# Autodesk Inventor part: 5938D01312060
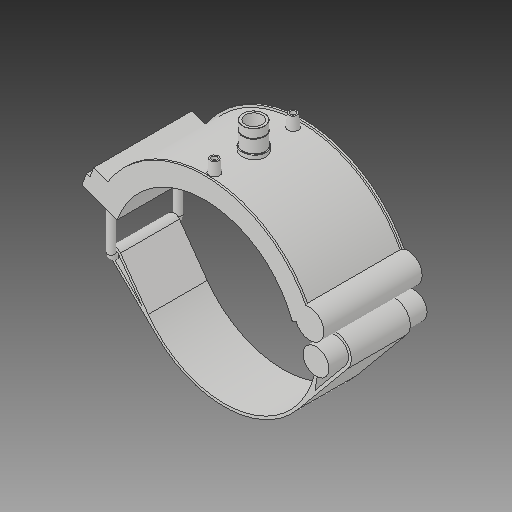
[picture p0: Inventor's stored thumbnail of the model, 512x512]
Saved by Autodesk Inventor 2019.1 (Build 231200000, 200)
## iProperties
Created: 2017-07
Part Number: 5938D01312060
Material: Generic
Description: PLASSON TRANSITION SADDLE 12''DIPS x 1"NPT
Document SubType Name: Modeling
Designer: KIM
Density: 1 g/cm^3
Appearance: Default
Author: KIM
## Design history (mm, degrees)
derived "5938D.ipt"
feature "Solid1::5938D.ipt"
tag "TaggingFeature1"
body "Solid1"
other parameters: "d_" = 333.8, "B_" = 194.818, "H_" = 46.736, "L_" = 176.022, "d_t" = 6, "G_" = 30.291, "d148" = 5.007, "d160" = 5.007, "d169" = 5.007, "d192" = 13.352, "d0" = 333.8, "d1" = 400.56, "d2" = 487.045, "d3" = 83.45, "d4" = 176.022, "d5" = 0, "d40" = 208.2912, "d41" = 42.4074, "d43" = 0, "d45" = 0, "d47" = 247.016, "d48" = 39.3783, "d50" = 0, "d78" = 222.28, "d79" = 15, "d80" = 70.4088, "d82" = 5 deg, "d84" = 4, "d85" = 14, "d86" = 0, "d87" = 3, "d88" = 0, "d96" = 408.5712, "d97" = 3.52044, "d98" = 0, "d102" = 0.90873, "d103" = 30.291, "d104" = 28.0416, "d105" = 0, "d106" = 24.2328, "d108" = 0, "d109" = -15.57867, "d111" = 0.5, "d112" = 0.5, "d113" = 0, "d114" = 0.5, "d117" = 0.30291, "d120" = 140 deg, "d121" = 24.228, "d122" = 20 deg, "d123" = 1602.24, "d124" = 240.336, "d126" = 0, "d143" = 343.814, "d145" = 51.35385, "d149" = 5.007, "d150" = 56.48923, "d153" = 176.022, "d154" = 0, "d156" = 200.28, "d157" = 160 deg, "d159" = 13.352, "d161" = 5.007, "d162" = 105.6132, "d163" = 0, "d164" = 166.9, "d167" = 33.38, "d168" = 195.39512, "d170" = 5.007, "d172" = 0, "d173" = 1, "d175" = 166.9, "d176" = 20 deg, "d177" = 23.366, "d178" = 66.76, "d180" = 0, "d183" = 26.704, "d184" = 18.6928, "d185" = 57.20715, "d186" = 57.20715, "d187" = 200.28, "d188" = 20.028, "d189" = 23.366, "d190" = 0, "d191" = 240.336, "d193" = 13.352, "d194" = 6.8429, "d195" = 90 deg, "d197" = 0, "d199" = 0
